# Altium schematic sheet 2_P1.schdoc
size 431 x 309 mm
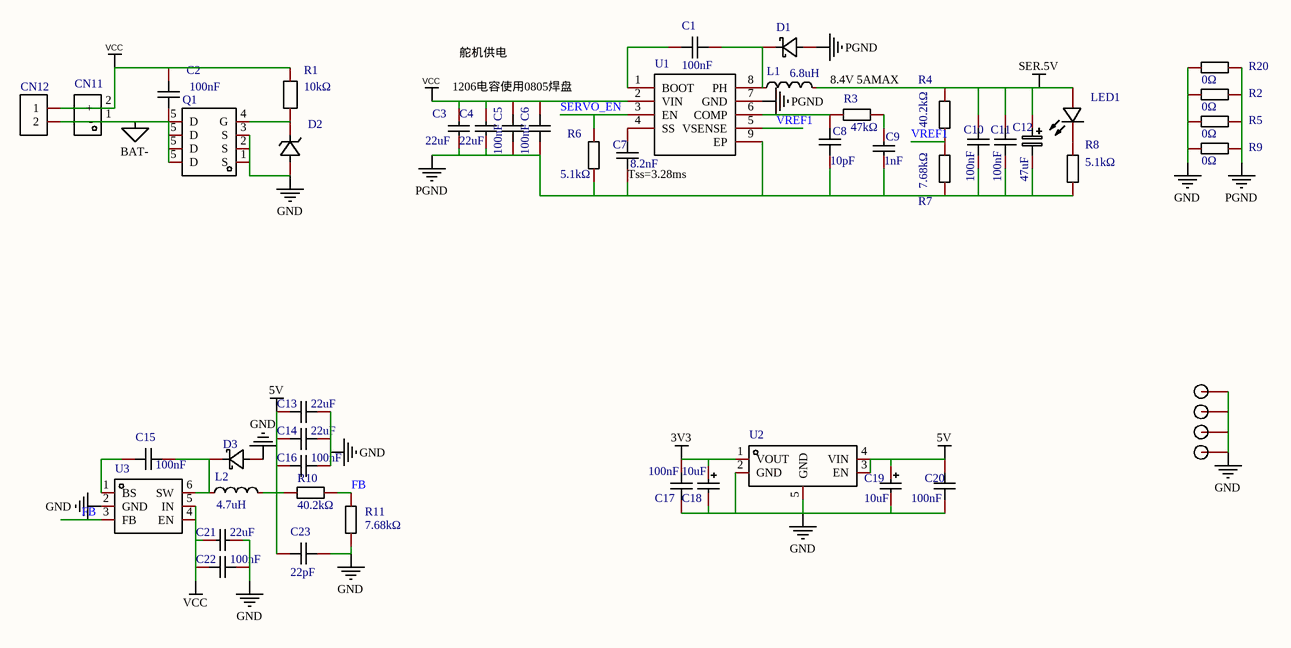
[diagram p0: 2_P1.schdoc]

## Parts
C1  value 100nF  [C0603]  (hidden comment: CC0603KRX7R9BB104)
C2  value 100nF  [C0603]  (hidden comment: CL10B104KC8NNNC)
C3  value 22uF  [C0805]  (hidden comment: C3216X5R1V226M160AC)
C4  value 22uF  [C0805]  (hidden comment: C3216X5R1V226M160AC)
C5  value 100nF  [C0603]  (hidden comment: CL10B104KC8NNNC)
C6  value 100nF  [C0603]  (hidden comment: CL10B104KC8NNNC)
C7  value 8.2nF  [C0603]  (hidden comment: 0603B822J500CT)
C8  value 10pF  [C0603]  (hidden comment: CC0603GRNPO9BN100)
C9  value 1nF  [C0603]  (hidden comment: CL10B102KB8NNNC)
C10  value 100nF  [C0603]  (hidden comment: CC0603KRX7R9BB104)
C11  value 100nF  [C0603]  (hidden comment: CC0603KRX7R9BB104)
C12  value 47uF  [CAP-SMD_L3.5-W2.8-R-RD]  (hidden comment: CA45-B-16V-47uF-K)
C13  value 22uF  [C0603]  (hidden comment: ZRB18AR60J226ME01L)
C14  value 22uF  [C0603]  (hidden comment: ZRB18AR60J226ME01L)
C15  value 100nF  [C0603]  (hidden comment: CL10B104KC8NNNC)
C16  value 100nF  [C0603]  (hidden comment: CL10B104KC8NNNC)
C17  value 100nF  [C0402]  (hidden comment: CGA2B3X7R1V104MT0Y0F)
C18  value 10uF  [CAP-SMD_L3.5-W2.8-R-RD]  (hidden comment: TC211B106K025Y)
C19  value 10uF  [CAP-SMD_L3.5-W2.8-R-RD]  (hidden comment: TC211B106K025Y)
C20  value 100nF  [C0402]  (hidden comment: CGA2B3X7R1V104MT0Y0F)
C21  value 22uF  [C0805]  (hidden comment: C3216X5R1V226M160AC)
C22  value 100nF  [C0603]  (hidden comment: CL10B104KC8NNNC)
C23  value 22pF  [C0603]  (hidden comment: GCM1885C2A220JA16D)
CN11  XT30UPB-M  [CONN-TH_XT30UPB-M]  (value not drawn)
CN12  XT30UPB-F  [CONN-TH_XT30UPB-F]  (value not drawn)
D1  DSK310  [SOD-123_L2.7-W1.8-LS3.7-RD]  (value not drawn)
D2  ZMM9V1  [LL-34_L3.5-W1.5-RD]  (value not drawn)
D3  DSK310  [SOD-123_L2.7-W1.8-LS3.7-RD]  (value not drawn)
H1  M2.5_M2.5  [M2.5]  (value not drawn)
H2  M2.5_M2.5  [M2.5]  (value not drawn)
H3  M2.5_M2.5  [M2.5]  (value not drawn)
H4  M2.5_M2.5  [M2.5]  (value not drawn)
L1  value 6.8uH  [IND-SMD_L6.6-W6.6]  (hidden comment: SMMS0630-6R8M)
L2  value 4.7uH  [IND-SMD_L4.5-W4.0-1]  (hidden comment: MCS0420-4R7MPN2)
LED1  NCD0805R1  [LED0805-RD_RED]  (value not drawn)
Q1  WSD3066DN33  [DFN-8_L3.3-W3.3-P0.65-BL]  (value not drawn)
R1  value 10kΩ  [R0603]  (hidden comment: AR03BTD1002)
R2  value 0Ω  [R0805]  (hidden comment: 0805W8F0000T5E)
R3  value 47kΩ  [R0603]  (hidden comment: RS-03K473JT)
R4  value 40.2kΩ  [R0603]  (hidden comment: TC0325B4022T5E)
R5  value 0Ω  [R0805]  (hidden comment: 0805W8F0000T5E)
R6  value 5.1kΩ  [R0603]  (hidden comment: RG1608P-512-B-T5)
R7  value 7.68kΩ  [R0603]  (hidden comment: RMC06037.68K1%N)
R8  value 5.1kΩ  [R0603]  (hidden comment: RMC06035.1K1%N)
R9  value 0Ω  [R0805]  (hidden comment: 0805W8F0000T5E)
R10  value 40.2kΩ  [R0603]  (hidden comment: TC0325B4022T5E)
R11  value 7.68kΩ  [R0603]  (hidden comment: RMC06037.68K1%N)
R20  value 0Ω  [R0805]  (hidden comment: 0805W8F0000T5E)
U1  TPS54531DDAR  [SOIC-8_L5.0-W4.0-P1.27-LS6.0-BL-EP2.0]  (value not drawn)
U2  SK6019AD4-33  [XDFN-4_L1.0-W1.0-P0.65-BL-EP]  (value not drawn)
U3  RY8411  [SOT-23-6_L2.9-W1.6-P0.95-LS2.8-TL]  (value not drawn)

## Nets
3V3: C17.2 C18.1 U2.1(VOUT)
5V: C13.1 C14.1 C16.1 C19.1 C20.2 C23.1 L2.2 R10.2 U2.3(EN) U2.4(VIN)
BAT-: C2.1 CN11.1(-) CN12.2 Q1.5(D)
GND: C13.2 C14.2 C16.2 C17.1 C18.2 C19.2 C20.1 C21.1 C22.2 C23.2 D2.2(A) D3.2(A) H1.1 H2.1 H3.1 H4.1 Q1.1(S) Q1.2(S) Q1.3(S) R2.1 R5.1 R9.1 R11.1 R20.1 U2.2(GND) U2.5(GND) U3.2(GND)
PGND: C3.1 C4.1 C5.1 C6.1 C7.1 C8.1 C9.1 C10.1 C11.1 C12.2 D1.2(A) R2.2 R5.2 R6.1 R7.1 R8.1 R9.2 R20.2 U1.7(GND) U1.9(EP)
SER.5V: C10.2 C11.2 C12.1 L1.2 LED1.2(+) R4.2
VCC: C2.2 C3.2 C4.2 C5.2 C6.2 C21.2 C22.1 CN11.2(+) CN12.1 R1.2 U1.2(VIN) U3.4(EN) U3.5(IN)
FB: R10.1 R11.2 U3.3(FB)
SERVO_EN: R6.2 U1.3(EN)
VREF1: R4.1 R7.2 U1.5(VSENSE)
NetC1_1: C1.1 U1.1(BOOT)
NetC1_2: C1.2 D1.1(K) L1.1 U1.8(PH)
NetC7_2: C7.2 U1.4(SS)
NetC8_2: C8.2 R3.1 U1.6(COMP)
NetC9_2: C9.2 R3.2
NetC15_1: C15.1 U3.1(BS)
NetC15_2: C15.2 D3.1(K) L2.1 U3.6(SW)
NetD2_1: D2.1(K) Q1.4(G) R1.1
NetLED1_1: LED1.1(-) R8.2

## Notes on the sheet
- 舵机供电
- 1206电容使用0805焊盘
- 8.4V 5AMAX
- (near C7) Tss=3.28ms

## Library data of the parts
C1 C10 C11 = CC0603KRX7R9BB104: 容值:100nF;精度:±10%;额定电压:50V;温度系数:X7R;; Manufacturer: YAGEO(国巨); Add into BOM: yes; Tolerance: ±10%; Voltage Rated: 50V; Temperature Coefficient: X7R
C2 C5 C6 C15 C16 C22 = CL10B104KC8NNNC: 容值:100nF;精度:±10%;额定电压:100V;温度系数:X7R;; Manufacturer: SAMSUNG(三星); Add into BOM: yes; Tolerance: ±10%; Voltage Rated: 100V; Temperature Coefficient: X7R
C3 C4 C21 = C3216X5R1V226M160AC: 容值:22uF;精度:±20%;额定电压:35V;温度系数:X5R;; Manufacturer: TDK; Add into BOM: yes; Tolerance: ±20%; Voltage Rated: 35V; Temperature Coefficient: X5R
C7 = 0603B822J500CT: 容值:8.2nF;精度:±5%;额定电压:50V;温度系数:X7R;; Manufacturer: 华新科(Walsin); Add into BOM: yes; Tolerance: ±5%; Voltage Rated: 50V; Temperature Coefficient: X7R
C8 = CC0603GRNPO9BN100: 容值:10pF;精度:±2%;额定电压:50V;温度系数:NP0;; Manufacturer: YAGEO(国巨); Add into BOM: yes; Tolerance: ±2%; Voltage Rated: 50V; Temperature Coefficient: NP0
C9 = CL10B102KB8NNNC: 容值:1nF;精度:±10%;额定电压:50V;温度系数:X7R;; Manufacturer: SAMSUNG(三星); Add into BOM: yes; Tolerance: ±10%; Voltage Rated: 50V; Temperature Coefficient: X7R
C12 = CA45-B-16V-47uF-K: 工作温度:-55~+125;等效串联电阻:3Ω 100kHz;容值:47uF;额定电压:16V;精度:±10%;; Manufacturer: CEC(振华新云); Add into BOM: yes; Rated Voltage: 16V; Tolerance: ±10%
C13 C14 = ZRB18AR60J226ME01L: 容值:22uF;精度:±20%;额定电压:-;材质(温度系数):-;; Manufacturer: muRata(村田); Add into BOM: yes; Tolerance: ±20%
C17 C20 = CGA2B3X7R1V104MT0Y0F: 容值:100nF;精度:±20%;额定电压:35V;温度系数:X7R;; Manufacturer: TDK; Add into BOM: yes; Tolerance: ±20%; Voltage Rated: 35V; Temperature Coefficient: X7R
C18 C19 = TC211B106K025Y: 容值:10uF;精度:±10%;额定电压:25V;等效串联电阻:3Ω@100kHz;工作温度:-55~+125;; Manufacturer: Sunlord(顺络); Add into BOM: yes; Tolerance: ±10%; Rated Voltage: 25V
C23 = GCM1885C2A220JA16D: 容值:22pF;精度:±5%;额定电压:100V;温度系数:C0G;; Manufacturer: muRata(村田); Add into BOM: yes; Tolerance: ±5%; Voltage Rated: 100V; Temperature Coefficient: C0G
CN11 = XT30UPB-M: Manufacturer: AMASS(艾迈斯); Add into BOM: yes
CN12 = XT30UPB-F: 模型插头连接器; Manufacturer: AMASS(艾迈斯); Add into BOM: yes
D1 D3 = DSK310: 二极管配置:-;直流反向耐压(Vr):100V;平均整流电流(Io):3A;正向压降(Vf):850mV@3A;反向电流(Ir):500A@100V;; Manufacturer: LGE(鲁光); Symbol: DSK310_C713648; Add into BOM: yes; Reverse Voltage (Vr): 100V; Average Rectified Current (Io): 3A
D2 = ZMM9V1: 稳压值(标称值):-;精度:-;功率:500mW;反向电流(Ir):100nA@6.8V;; Manufacturer: Slkor(萨科微); Symbol: ZMM9V1_C707200; Add into BOM: yes; Power Dissipation: 500mW
H1-H4 = M2.5_M2.5: Convert to PCB: yes
L1 = SMMS0630-6R8M: 电感值:6.8uH;精度:±20%;额定电流:-;直流电阻(DCR):-;; Manufacturer: SXN(顺翔诺); Add into BOM: yes; Tolerance: ±20%
L2 = MCS0420-4R7MPN2: 电感值:4.7uH;精度:±20%;额定电流:2.2A;饱和电流(Isat):3.5A;直流电阻(DCR):98mΩ;; Manufacturer: PSA(信昌电陶); Add into BOM: yes; Tolerance: ±20%; Rated Current: 2.2A; Saturation Current (Isat): 3.5A; DC Resistance (DCR): 98mΩ
LED1 = NCD0805R1: 发光颜色:红灯;; Manufacturer: 国星光电; Symbol: FC-2012HRK-620D; Add into BOM: yes; Emitted Color: 红灯
Q1 = WSD3066DN33: 类型:N沟道;漏源电压(Vdss):30V;连续漏极电流(Id):50A;功率(Pd):45W;导通电阻(RDS(on)@Vgs,Id):5.7mΩ@10V,35A;阈值电压(Vgs(th)@Id):2.5V@250A;; Manufacturer: WINSOK微硕; Add into BOM: yes; Type: N沟道; Drain Source Voltage (Vdss): 30V; Continuous Drain Current (Id): 50A; Power Dissipation (Pd): 45W
R1 = AR03BTD1002: 阻值:10kΩ;精度:±0.01%;功率:-;温度系数:±50ppm/;最大工作电压:50V;工作温度范围:-55~+125;; Manufacturer: Viking(光颉); Add into BOM: yes; Tolerance: ±0.01%; Temperature Coefficient: ±50ppm/; Overload Voltage (Max): 50V
R2 R5 R9 R20 = 0805W8F0000T5E: 精度:±1%;温度系数:±800ppm/;阻值:0Ω;功率:0.125W;; Manufacturer: UNI-ROYAL(厚声); Add into BOM: yes; Tolerance: ±1%; Power(Watts): 0.125W
R3 = RS-03K473JT: 阻值:47kΩ;精度:±5%;功率:100mW;温度系数:±100ppm/;最大工作电压:50V;工作温度范围:-55~+155;; Manufacturer: FH(风华); Add into BOM: yes; Tolerance: ±5%; Power(Watts): 100mW; Overload Voltage (Max): 50V
R4 R10 = TC0325B4022T5E: 阻值:40.2kΩ;精度:±0.1%;功率:1/6W;温度系数:±25ppm/;最大工作电压:75V;工作温度范围:-55~+155;; Manufacturer: UNI-ROYAL(厚声); Add into BOM: yes; Tolerance: ±0.1%; Power(Watts): 1/6W; Temperature Coefficient: ±25ppm/; Overload Voltage (Max): 75V
R6 = RG1608P-512-B-T5: 电阻类型:金属膜电阻;阻值:5.1kΩ;精度:±0.1%;功率:100mW;温度系数:±25ppm/;最大工作电压:100V;工作温度范围:-55~+155;; Manufacturer: SUSUMU; Add into BOM: yes; Tolerance: ±0.1%; Power(Watts): 100mW; Temperature Coefficient: ±25ppm/; Overload Voltage (Max): 100V
R7 R11 = RMC06037.68K1%N: 阻值:7.68kΩ;精度:±1%;功率:0.1W;; Manufacturer: Tyohm(幸亚电阻); Add into BOM: yes; Tolerance: ±1%; Power(Watts): 0.1W
R8 = RMC06035.1K1%N: 阻值:5.1kΩ;精度:±1%;功率:0.1W;; Manufacturer: Tyohm(幸亚电阻); Add into BOM: yes; Tolerance: ±1%; Power(Watts): 0.1W
U1 = TPS54531DDAR: 功能类型:降压型;同步整流:-;输出通道数:-;拓扑结构:-;输入电压:-;输出电流(最大值):-;开关频率:-;; Manufacturer: TI(德州仪器); Add into BOM: yes; Function: 降压型
U2 = SK6019AD4-33: 输出类型:-;; Manufacturer: 洺太电子(suntek); Add into BOM: yes
U3 = RY8411: Manufacturer: RYCHiP(蕊源); Symbol: RY8411_C2935411; Add into BOM: yes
